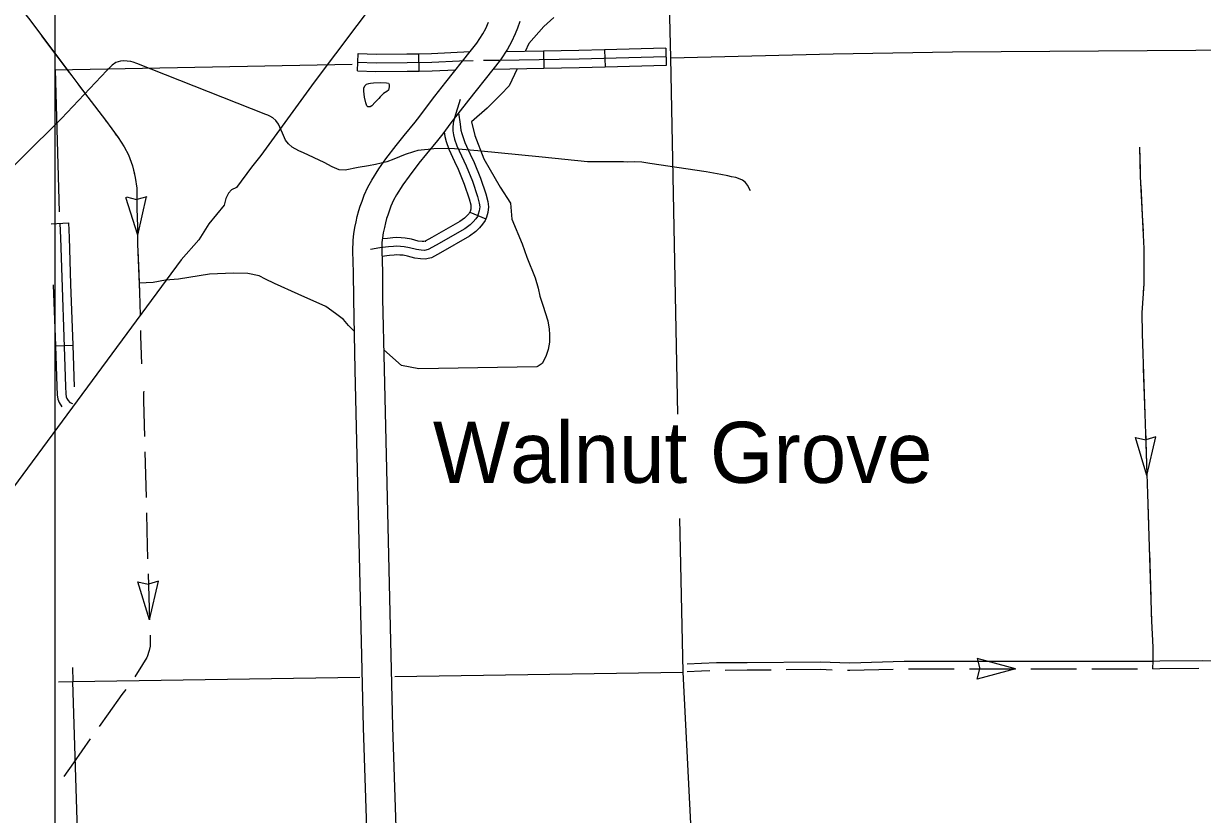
# Model space of a CAD drawing. Extents: x -5566 to 1759129, y -3726 to 731467.
# Drawn here: x -5021.1 to -4943.7, y 380.4 to 432.3 of the extents above; entities that cross this region are included whole.
import ezdxf

# ---------------------------------------------------------------- set-up
doc = ezdxf.new("R2010")
doc.units = 0
doc.layers.add('Default', color=7, linetype='Continuous')
doc.layers.add('R_No Plot', color=7, linetype='Continuous')

msp = doc.modelspace()

# ---------------------------------------------------------------- linework, layer by layer
at = {"layer": 'Default'}
for p, q in [((-4999.148, 429.219), (-4999.112, 430.357)), ((-4995.112, 429.206), (-4995.13, 430.345)), ((-4986.944, 430.515), (-4986.926, 429.376)), ((-4982.942, 430.598), (-4982.911, 429.459)), ((-4978.933, 430.707), (-4978.903, 429.568)), ((-5013.561, 418.438), (-5014.357, 420.92)), ((-5014.321, 420.954), (-5013.65, 420.774)), ((-5012.971, 420.954), (-5013.641, 420.774)), ((-5013.561, 418.438), (-5013.01, 420.985)), ((-4991.792, 419.951), (-4990.738, 419.517)), ((-5019.267, 419.19), (-5018.129, 419.243)), ((-5018.977, 411.183), (-5017.838, 411.222)), ((-4947.354, 402.671), (-4948.114, 405.164)), ((-4948.114, 405.164), (-4947.438, 405.008)), ((-4946.766, 405.21), (-4947.429, 405.008)), ((-4947.354, 402.671), (-4946.766, 405.21)), ((-5012.813, 393.205), (-5013.559, 395.702)), ((-5013.559, 395.702), (-5012.884, 395.542)), ((-5012.21, 395.74), (-5012.875, 395.542)), ((-5012.813, 393.205), (-5012.21, 395.74)), ((-4955.983, 389.99), (-4958.501, 390.665)), ((-4958.501, 390.665), (-4958.322, 389.996)), ((-4955.983, 389.99), (-4958.501, 389.316)), ((-4958.501, 389.316), (-4958.321, 389.986))]:
    msp.add_line(p, q, dxfattribs=at)
for points in [[(-4961.675, 482.918), (-4977.298, 461.739), (-4977.613, 461.074), (-4983.614, 452.875), (-4992.136, 441.608), (-5001.998, 428.477), (-5005.489, 423.669), (-5006.101, 422.9), (-5007.104, 421.562), (-5007.426, 421.423), (-5007.616, 421.188), (-5007.787, 420.845), (-5007.905, 420.412), (-5008.915, 419.184), (-5009.574, 418.146), (-5010.73, 416.827), (-5024.394, 398.311), (-5035.962, 382.902), (-5037.28, 381.083), (-5049.286, 365.134), (-5058.586, 352.693)], [(-4978.934, 442.5), (-4978.61, 430.074)], [(-5023.778, 436.756), (-5021.989, 434.264), (-5020.738, 432.673), (-5017.908, 428.892), (-5016.86, 427.493), (-5015.698, 425.982), (-5014.864, 424.842), (-5014.458, 424.234), (-5014.189, 423.718), (-5013.917, 422.993), (-5013.736, 422.237), (-5013.646, 421.526), (-5013.646, 420.184), (-5013.59, 419.022), (-5013.59, 417.874), (-5013.455, 414.691)], [(-4999.405, 414.268), (-4999.415, 415.992), (-4999.461, 417.391), (-4999.447, 418.117), (-4999.389, 418.532), (-4999.332, 418.941), (-4999.24, 419.328), (-4999.177, 419.677), (-4999.064, 420.069), (-4998.977, 420.356), (-4998.858, 420.681), (-4998.717, 421.057), (-4998.483, 421.589), (-4998.223, 422.05), (-4997.753, 422.8), (-4997.293, 423.445), (-4996.626, 424.323), (-4996.104, 424.983), (-4995.381, 425.856), (-4995.06, 426.248), (-4994.556, 426.934), (-4994.088, 427.561), (-4993.367, 428.485), (-4991.762, 430.492), (-4991.33, 431.051), (-4990.935, 431.654), (-4990.733, 431.996), (-4990.55, 432.414)], [(-4988.514, 432.454), (-4988.655, 432.021), (-4988.805, 431.664), (-4989.04, 431.128), (-4989.323, 430.651), (-4989.782, 429.948), (-4990.27, 429.318), (-4991.877, 427.309), (-4992.578, 426.409), (-4993.031, 425.803), (-4993.56, 425.084), (-4993.914, 424.65), (-4994.628, 423.788), (-4995.126, 423.159), (-4995.764, 422.32), (-4996.174, 421.744), (-4996.591, 421.08), (-4996.783, 420.739), (-4996.958, 420.341), (-4997.077, 420.023), (-4997.176, 419.753), (-4997.244, 419.528), (-4997.326, 419.244), (-4997.381, 418.94), (-4997.464, 418.591), (-4997.508, 418.272), (-4997.551, 417.967), (-4997.561, 417.404), (-4997.517, 416.029), (-4997.506, 414.279)], [(-4986.276, 432.726), (-4986.924, 432.134), (-4987.911, 431.01), (-4988.149, 430.495)], [(-5019.885, 431.533), (-5018.083, 429.125)], [(-4999.112, 430.357), (-4997.927, 430.319), (-4995.913, 430.333), (-4995.13, 430.345)], [(-4995.13, 430.345), (-4994.297, 430.357), (-4991.767, 430.486)], [(-4978.918, 430.137), (-4984.615, 429.983), (-4989.867, 429.898), (-4990.879, 429.904)], [(-4986.944, 430.515), (-4989.427, 430.474)], [(-4982.942, 430.598), (-4984.627, 430.553), (-4986.944, 430.515)], [(-4978.933, 430.707), (-4982.942, 430.598)], [(-4978.61, 430.074), (-4967.942, 430.337), (-4960.109, 430.466), (-4937.75, 430.615)], [(-4984.057, 423.254), (-4987.048, 423.568), (-4991.253, 423.978), (-4992.8, 424.112), (-4993.205, 424.121), (-4994.143, 424.102), (-4994.523, 424.055), (-4994.769, 424.05), (-4995.187, 423.996), (-4995.482, 423.904), (-4996.038, 423.735), (-4996.778, 423.422), (-4997.222, 423.25), (-4997.981, 423.084), (-4998.423, 422.996), (-4999.114, 422.886), (-4999.954, 422.705), (-5000.362, 422.733), (-5000.824, 422.918), (-5001.345, 423.202), (-5002.698, 423.854), (-5003.006, 423.986), (-5003.44, 424.218), (-5003.694, 424.445), (-5003.87, 424.683), (-5004.075, 425.138), (-5004.34, 425.729), (-5004.51, 425.964), (-5004.714, 426.15), (-5004.908, 426.246), (-5005.044, 426.317), (-5005.174, 426.358), (-5013.631, 429.705), (-5013.883, 429.799), (-5014.029, 429.833), (-5014.268, 429.86), (-5014.478, 429.881), (-5014.711, 429.85), (-5015.015, 429.766), (-5015.263, 429.601), (-5015.468, 429.386), (-5015.596, 429.246), (-5018.576, 426.098), (-5023.741, 420.998)], [(-5019.003, 429.298), (-4999.498, 429.673)], [(-4999.13, 429.788), (-4997.934, 429.75), (-4995.907, 429.763), (-4994.278, 429.788), (-4992.463, 429.88), (-4991.57, 429.896)], [(-4988.68, 429.347), (-4989.195, 428.234), (-4989.75, 427.679), (-4990.651, 426.777), (-4991.675, 425.888), (-4991.457, 424.983), (-4990.875, 423.455), (-4989.784, 421.601), (-4989.112, 420.551)], [(-4986.926, 429.376), (-4990.267, 429.321)], [(-4982.911, 429.459), (-4984.602, 429.414), (-4986.926, 429.376)], [(-4978.903, 429.568), (-4982.911, 429.459)], [(-4978.61, 430.074), (-4978.151, 406.69)], [(-5019.003, 429.298), (-5018.731, 419.965)], [(-4999.148, 429.219), (-4997.942, 429.18), (-4995.901, 429.194), (-4995.112, 429.206)], [(-4995.112, 429.206), (-4994.26, 429.219), (-4992.718, 429.297)], [(-5017.482, 428.323), (-5016.86, 427.493), (-5015.698, 425.982), (-5015.66, 425.93)], [(-4997.757, 427.408), (-4997.997, 427.169), (-4998.216, 426.936), (-4998.316, 426.863), (-4998.375, 426.856), (-4998.468, 426.863), (-4998.535, 426.93), (-4998.608, 427.116), (-4998.701, 427.488), (-4998.748, 427.887), (-4998.748, 428.08), (-4998.681, 428.24), (-4998.555, 428.353), (-4998.422, 428.393), (-4998.309, 428.412), (-4998.11, 428.439)], [(-4998.11, 428.439), (-4997.677, 428.459), (-4997.245, 428.439), (-4997.112, 428.419), (-4997.073, 428.339), (-4997.073, 428.299), (-4997.073, 428.166), (-4997.119, 427.967), (-4997.232, 427.861), (-4997.445, 427.728), (-4997.671, 427.515), (-4997.757, 427.408)], [(-4992.426, 427.347), (-4992.785, 426.137), (-4992.878, 425.794), (-4992.894, 425.501), (-4992.894, 425.292), (-4992.861, 425.016), (-4992.794, 424.748), (-4992.635, 424.313), (-4992.028, 422.99), (-4991.619, 421.994), (-4991.284, 420.982), (-4991.167, 420.546), (-4991.133, 420.304), (-4991.167, 420.036), (-4991.234, 419.81), (-4991.292, 419.668), (-4991.401, 419.509), (-4991.56, 419.316), (-4991.761, 419.124), (-4992.12, 418.864), (-4993.994, 417.785), (-4994.512, 417.503), (-4994.76, 417.446), (-4994.97, 417.461), (-4995.29, 417.491), (-4995.734, 417.62), (-4996.094, 417.687), (-4996.331, 417.706), (-4996.566, 417.72), (-4996.794, 417.707), (-4997.127, 417.668), (-4997.7, 417.601), (-4998.302, 417.492)], [(-4992.537, 426.462), (-4992.419, 425.727), (-4992.37, 425.324), (-4992.3, 425.119), (-4992.249, 424.915), (-4992.108, 424.529), (-4991.754, 423.757)], [(-5015.068, 425.121), (-5014.864, 424.842), (-5014.458, 424.234), (-5014.189, 423.718), (-5013.917, 422.993), (-5013.783, 422.435)], [(-4993.459, 425.22), (-4993.422, 424.912), (-4993.339, 424.581), (-4993.162, 424.096), (-4992.789, 423.283)], [(-4947.84, 424.208), (-4947.793, 422.292), (-4947.661, 419.755), (-4947.549, 417.576), (-4947.567, 415.247), (-4947.68, 413.349), (-4947.67, 411.962), (-4947.314, 401.479), (-4947.056, 393.116), (-4946.971, 391.416), (-4946.971, 390.505), (-4946.99, 389.988)], [(-4947.84, 424.208), (-4947.803, 422.705)], [(-4992.789, 423.283), (-4992.551, 422.763), (-4992.153, 421.796), (-4991.83, 420.818), (-4991.726, 420.433), (-4991.708, 420.3), (-4991.726, 420.153), (-4991.772, 420), (-4991.792, 419.951)], [(-4991.754, 423.757), (-4991.506, 423.217), (-4991.084, 422.192), (-4990.738, 421.145), (-4990.608, 420.66), (-4990.559, 420.307), (-4990.607, 419.919), (-4990.696, 419.62), (-4990.738, 419.517)], [(-4973.366, 421.349), (-4973.557, 421.731), (-4973.693, 421.901), (-4973.892, 422.049), (-4974.042, 422.118), (-4974.321, 422.223), (-4974.614, 422.281), (-4974.845, 422.333), (-4975.306, 422.423), (-4976.28, 422.594), (-4979.967, 423.156), (-4980.491, 423.232), (-4980.989, 423.265), (-4981.46, 423.243), (-4981.694, 423.249), (-4982.57, 423.248), (-4984.057, 423.254)], [(-4947.762, 421.703), (-4947.661, 419.755), (-4947.607, 418.7)], [(-5013.646, 421.443), (-5013.646, 420.184), (-5013.59, 419.022), (-5013.59, 418.437)], [(-4989.112, 420.551), (-4989.031, 419.499), (-4988.343, 417.873), (-4988.035, 416.99), (-4987.492, 415.642), (-4987.305, 414.969), (-4987.182, 414.446), (-4987.005, 413.849), (-4986.669, 412.823), (-4986.584, 412.276), (-4986.558, 411.918), (-4986.566, 411.423), (-4986.65, 410.947), (-4986.775, 410.539), (-4986.903, 410.261), (-4987.033, 410.028), (-4987.159, 409.925), (-4987.301, 409.837), (-4987.399, 409.811), (-4995.136, 409.663), (-4996.271, 409.893), (-4997.434, 410.916)], [(-4991.792, 419.951), (-4991.796, 419.94), (-4991.857, 419.852), (-4991.978, 419.704), (-4992.126, 419.562), (-4992.43, 419.343), (-4994.273, 418.282), (-4994.716, 418.041), (-4994.663, 418.053)], [(-4990.738, 419.517), (-4990.788, 419.396), (-4990.945, 419.166), (-4991.142, 418.928), (-4991.395, 418.685), (-4991.811, 418.385), (-4993.716, 417.288), (-4994.308, 416.966), (-4994.405, 416.944)], [(-5018.698, 419.217), (-5018.652, 418.258), (-5018.314, 408.521), (-5018.3, 408.024), (-5018.263, 407.838), (-5018.219, 407.72), (-5018.137, 407.594), (-5018.041, 407.46), (-5017.848, 407.394)], [(-5018.129, 419.243), (-5018.083, 418.281), (-5017.977, 415.23)], [(-4994.663, 418.053), (-4994.805, 418.02), (-4994.922, 418.028), (-4995.183, 418.053), (-4995.602, 418.175), (-4996.019, 418.252), (-4996.29, 418.274), (-4996.566, 418.291), (-4996.844, 418.274), (-4997.193, 418.233), (-4997.519, 418.195)], [(-5013.571, 417.435), (-5013.508, 415.933)], [(-4994.405, 416.944), (-4994.715, 416.871), (-4995.017, 416.893), (-4995.398, 416.929), (-4995.866, 417.066), (-4996.169, 417.122), (-4996.371, 417.138), (-4996.566, 417.15), (-4996.744, 417.139), (-4997.061, 417.102), (-4997.55, 417.045)], [(-4947.555, 417.699), (-4947.549, 417.576), (-4947.567, 415.247), (-4947.6, 414.693)], [(-5013.508, 415.933), (-5013.455, 414.691)], [(-4999.359, 412.123), (-4999.743, 412.518), (-5000.07, 412.901), (-5000.589, 413.307), (-5001.243, 413.77), (-5003.058, 414.571), (-5004.592, 415.281), (-5005.189, 415.552), (-5005.599, 415.782), (-5006.352, 415.921), (-5007.299, 415.949), (-5008.859, 415.893), (-5010.895, 415.552), (-5011.763, 415.496), (-5012.564, 415.338), (-5013.481, 415.303)], [(-5019.116, 415.19), (-5018.977, 411.183)], [(-5017.977, 415.23), (-5017.838, 411.222)], [(-5013.455, 414.691), (-5013.423, 413.188)], [(-4993.615, 310.476), (-4995.511, 310.392), (-4996.003, 321.585), (-4997.259, 349.695), (-4998.481, 377.677), (-4998.548, 379.506), (-4998.756, 386.137), (-4999.305, 409.605), (-4999.405, 414.253)], [(-4997.507, 414.294), (-4997.407, 409.647), (-4996.858, 386.189), (-4996.65, 379.571), (-4996.584, 377.753), (-4995.362, 349.779), (-4994.106, 321.669), (-4993.615, 310.476)], [(-4947.66, 413.692), (-4947.68, 413.349), (-4947.67, 411.962), (-4947.627, 410.686)], [(-5013.402, 412.185), (-5013.394, 411.805), (-5013.32, 410.009)], [(-5018.977, 411.183), (-5018.884, 408.503), (-5018.868, 407.96), (-5018.813, 407.682), (-5018.73, 407.462), (-5018.548, 407.179)], [(-5017.838, 411.222), (-5017.743, 408.497)], [(-4947.593, 409.684), (-4947.491, 406.679)], [(-5013.184, 408.202), (-5013.194, 408.113), (-5013.208, 407.572), (-5013.129, 405.23)], [(-4947.457, 405.677), (-4947.354, 402.671)], [(-5013.1, 404.228), (-5013.03, 401.221)], [(-4947.32, 401.67), (-4947.314, 401.479), (-4947.273, 400.167)], [(-5013.006, 400.219), (-5012.979, 399.052), (-5012.927, 397.213)], [(-4947.273, 400.167), (-4947.227, 398.664)], [(-4978.017, 399.849), (-4977.818, 389.769)], [(-4947.196, 397.662), (-4947.103, 394.656)], [(-5012.898, 396.211), (-5012.813, 393.205)], [(-4947.072, 393.654), (-4947.056, 393.116), (-4946.971, 391.416), (-4946.971, 390.649)], [(-5012.769, 392.204), (-5012.756, 391.942), (-5012.764, 391.475), (-5012.816, 391.185), (-5012.956, 390.77), (-5012.978, 390.734)], [(-5012.978, 390.734), (-5013.26, 390.273), (-5013.777, 389.46)], [(-5017.859, 390.063), (-5017.832, 389.148)], [(-4977.532, 390.314), (-4976.58, 390.353), (-4975.596, 390.391), (-4973.594, 390.41), (-4968.804, 390.449), (-4966.85, 390.385), (-4963.274, 390.487), (-4946.99, 390.483), (-4946.514, 390.505), (-4943.714, 390.53), (-4942.68, 390.512), (-4940.64, 390.553)], [(-4977.532, 389.819), (-4976.58, 389.858), (-4976.029, 389.879)], [(-4975.027, 389.902), (-4973.594, 389.915), (-4972.02, 389.928)], [(-4971.017, 389.936), (-4968.804, 389.954), (-4968.011, 389.928)], [(-4967.009, 389.895), (-4966.85, 389.89), (-4964.003, 389.971)], [(-4963.001, 389.992), (-4959.993, 389.991)], [(-4958.991, 389.991), (-4955.983, 389.99)], [(-4954.981, 389.99), (-4953.477, 389.99)], [(-4953.477, 389.99), (-4951.974, 389.989)], [(-4950.971, 389.989), (-4947.964, 389.989)], [(-4946.962, 389.99), (-4946.514, 390.009), (-4943.955, 390.033)], [(-5018.78, 389.131), (-5017.832, 389.148)], [(-5017.832, 389.148), (-4999.006, 389.44)], [(-5016.581, 349.233), (-5017.832, 389.148)], [(-4996.71, 389.476), (-4977.818, 389.769)], [(-4977.818, 389.769), (-4975.835, 350.875)], [(-5014.35, 388.64), (-5014.624, 388.309), (-5015.506, 387.041), (-5016.117, 386.208)], [(-5016.698, 385.391), (-5017.783, 383.825), (-5018.419, 382.925)]]:
    msp.add_lwpolyline(points, dxfattribs=at)
at = {"layer": 'R_No Plot'}
msp.add_lwpolyline([(-5018.988, 168.239), (-5018.988, 511.979), (-4446.603, 511.979), (-4446.603, 160.504), (-4913.433, 160.504)], dxfattribs=at)

# ---------------------------------------------------------------- texts
at = {"layer": 'Default'}
msp.add_text('Walnut Grove', height=4.00974, dxfattribs=at).set_placement((-4994.206, 402.187))

doc.saveas('drawing.dxf')
